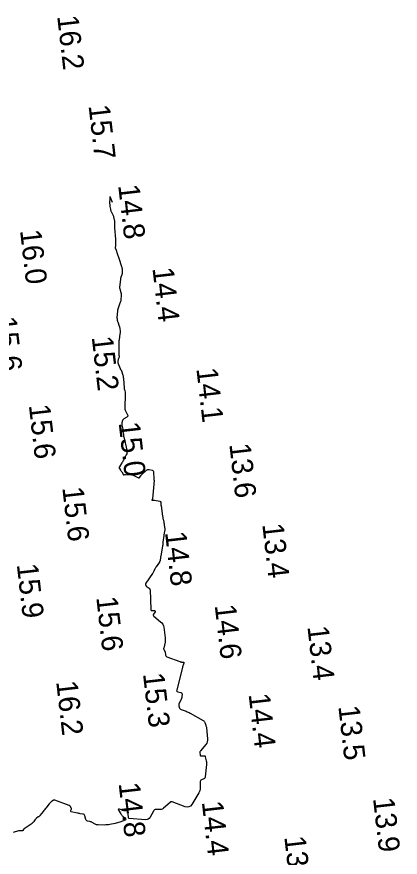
# Model space of a CAD drawing. Extents: x 1023796 to 1112670, y 656573 to 837340.
# Drawn here: x 1109935 to 1110025.3, y 681139.7 to 681337.8 of the extents above; entities that cross this region are included whole.
import ezdxf

# ---------------------------------------------------------------- set-up
doc = ezdxf.new("R2010")
doc.units = 0
doc.layers.add('V-CHAN-CONT-15FT', color=7, linetype='Continuous')
doc.layers.add('V-TOPO-SOUN', color=7, linetype='Continuous')

msp = doc.modelspace()

# ---------------------------------------------------------------- linework, layer by layer
at = {"layer": 'V-CHAN-CONT-15FT'}
msp.add_lwpolyline([(1109957.51, 681294.05), (1109957.04, 681295.22), (1109956.98, 681295.37), (1109956.93, 681295.41), (1109956.9, 681295.35), (1109956.88, 681295.19), (1109956.87, 681293.8), (1109956.88, 681293.64), (1109956.88, 681293.48), (1109956.9, 681293.31), (1109956.93, 681293.15), (1109957.04, 681292.51), (1109957.07, 681292.35), (1109957.12, 681292.19), (1109957.18, 681292.04), (1109957.24, 681291.9), (1109957.55, 681291.29), (1109957.62, 681291.14), (1109957.69, 681290.99), (1109957.74, 681290.83), (1109957.78, 681290.67), (1109957.95, 681289.97), (1109957.99, 681289.81), (1109958.01, 681289.66), (1109958.02, 681289.51), (1109958.02, 681289.36), (1109958.02, 681288.74), (1109958.02, 681288.59), (1109958.03, 681288.43), (1109958.03, 681288.28), (1109958.04, 681288.12), (1109958.24, 681285.41), (1109958.25, 681285.27), (1109958.26, 681285.13), (1109958.26, 681284.98), (1109958.26, 681284.84), (1109958.26, 681284.13), (1109958.25, 681284.05), (1109958.25, 681283.98), (1109958.24, 681283.9), (1109958.23, 681283.82), (1109958.18, 681283.43), (1109958.18, 681283.4), (1109958.18, 681283.37), (1109958.19, 681283.34), (1109958.2, 681283.3), (1109958.25, 681283.18), (1109958.26, 681283.15), (1109958.27, 681283.12), (1109958.28, 681283.09), (1109958.3, 681283.06), (1109958.73, 681281.81), (1109958.8, 681281.6), (1109958.88, 681281.38), (1109958.95, 681281.16), (1109959.03, 681280.94), (1109959.69, 681278.95), (1109959.74, 681278.78), (1109959.77, 681278.62), (1109959.79, 681278.45), (1109959.8, 681278.29), (1109959.82, 681277.56), (1109959.82, 681277.42), (1109959.8, 681277.28), (1109959.77, 681277.14), (1109959.73, 681277), (1109959.54, 681276.46), (1109959.5, 681276.32), (1109959.46, 681276.19), (1109959.43, 681276.05), (1109959.41, 681275.91), (1109959.21, 681274.11), (1109959.2, 681274.02), (1109959.21, 681273.93), (1109959.22, 681273.84), (1109959.24, 681273.75), (1109959.35, 681273.39), (1109959.37, 681273.3), (1109959.4, 681273.21), (1109959.42, 681273.13), (1109959.45, 681273.04), (1109959.55, 681272.61), (1109959.58, 681272.51), (1109959.59, 681272.4), (1109959.59, 681272.3), (1109959.59, 681272.2), (1109959.49, 681271.12), (1109959.47, 681270.9), (1109959.42, 681270.69), (1109959.37, 681270.49), (1109959.3, 681270.29), (1109958.94, 681269.36), (1109958.87, 681269.13), (1109958.8, 681268.9), (1109958.76, 681268.67), (1109958.73, 681268.44), (1109958.6, 681266.98), (1109958.6, 681266.89), (1109958.6, 681266.8), (1109958.61, 681266.71), (1109958.62, 681266.62), (1109958.68, 681266.26), (1109958.7, 681266.17), (1109958.72, 681266.09), (1109958.75, 681266), (1109958.78, 681265.91), (1109959.14, 681264.94), (1109959.19, 681264.79), (1109959.22, 681264.63), (1109959.25, 681264.48), (1109959.27, 681264.32), (1109959.32, 681263.69), (1109959.33, 681263.53), (1109959.33, 681263.37), (1109959.32, 681263.22), (1109959.3, 681263.06), (1109959.1, 681261.71), (1109959.06, 681261.44), (1109959.03, 681261.16), (1109959.02, 681260.88), (1109959.01, 681260.6), (1109959.02, 681258.24), (1109959.03, 681258.19), (1109959.03, 681258.14), (1109959.04, 681258.08), (1109959.05, 681258.03), (1109959.11, 681257.83), (1109959.12, 681257.78), (1109959.13, 681257.73), (1109959.12, 681257.68), (1109959.1, 681257.63), (1109958.96, 681257.3), (1109958.93, 681257.23), (1109958.9, 681257.16), (1109958.88, 681257.09), (1109958.86, 681257.01), (1109958.79, 681256.64), (1109958.78, 681256.55), (1109958.79, 681256.46), (1109958.8, 681256.38), (1109958.82, 681256.3), (1109959.33, 681254.9), (1109959.35, 681254.85), (1109959.38, 681254.8), (1109959.41, 681254.76), (1109959.44, 681254.71), (1109959.57, 681254.54), (1109959.61, 681254.5), (1109959.63, 681254.45), (1109959.66, 681254.4), (1109959.67, 681254.35), (1109959.97, 681253.35), (1109960.02, 681253.16), (1109960.06, 681252.97), (1109960.09, 681252.78), (1109960.11, 681252.59), (1109960.3, 681250.27), (1109960.3, 681250.22), (1109960.31, 681250.17), (1109960.32, 681250.12), (1109960.33, 681250.07), (1109960.39, 681249.89), (1109960.4, 681249.84), (1109960.41, 681249.79), (1109960.42, 681249.74), (1109960.43, 681249.7), (1109960.5, 681249.3), (1109960.51, 681249.22), (1109960.52, 681249.13), (1109960.53, 681249.05), (1109960.53, 681248.97), (1109960.47, 681245.54), (1109960.48, 681245.33), (1109960.52, 681245.14), (1109960.58, 681244.95), (1109960.67, 681244.76), (1109961.09, 681243.99), (1109961.15, 681243.84), (1109961.14, 681243.7), (1109961.08, 681243.59), (1109960.95, 681243.49), (1109960.24, 681243.09), (1109960.13, 681243.01), (1109960.03, 681242.91), (1109959.96, 681242.8), (1109959.92, 681242.67), (1109959.78, 681242.1), (1109959.75, 681241.96), (1109959.74, 681241.82), (1109959.75, 681241.68), (1109959.77, 681241.54), (1109959.99, 681240.59), (1109959.99, 681240.55), (1109959.98, 681240.51), (1109959.96, 681240.47), (1109959.93, 681240.45), (1109959.76, 681240.34), (1109959.73, 681240.31), (1109959.72, 681240.28), (1109959.73, 681240.25), (1109959.75, 681240.22), (1109959.95, 681240.02), (1109959.98, 681239.97), (1109960.01, 681239.92), (1109960.04, 681239.87), (1109960.05, 681239.81), (1109960.11, 681239.26), (1109960.12, 681239.14), (1109960.14, 681239.03), (1109960.16, 681238.92), (1109960.19, 681238.81), (1109960.91, 681235.65), (1109960.95, 681235.37), (1109960.95, 681235.1), (1109960.89, 681234.84), (1109960.79, 681234.59), (1109960.21, 681233.46), (1109960.11, 681233.26), (1109960, 681233.07), (1109959.89, 681232.88), (1109959.77, 681232.69), (1109959.19, 681231.76), (1109959.14, 681231.66), (1109959.12, 681231.56), (1109959.14, 681231.46), (1109959.19, 681231.36), (1109959.45, 681230.96), (1109959.52, 681230.86), (1109959.58, 681230.76), (1109959.65, 681230.66), (1109959.71, 681230.56), (1109960.15, 681229.89), (1109960.18, 681229.86), (1109960.21, 681229.84), (1109960.24, 681229.84), (1109960.28, 681229.85), (1109960.43, 681229.92), (1109960.47, 681229.94), (1109960.51, 681229.95), (1109960.55, 681229.95), (1109960.59, 681229.95), (1109962, 681229.85), (1109962.2, 681229.82), (1109962.39, 681229.78), (1109962.57, 681229.71), (1109962.76, 681229.63), (1109963.63, 681229.16), (1109963.72, 681229.13), (1109963.8, 681229.13), (1109963.88, 681229.17), (1109963.94, 681229.25), (1109964.18, 681229.62), (1109964.24, 681229.71), (1109964.31, 681229.8), (1109964.39, 681229.88), (1109964.47, 681229.96), (1109965.56, 681230.94), (1109965.7, 681231.03), (1109965.85, 681231.09), (1109966.01, 681231.11), (1109966.17, 681231.1), (1109966.87, 681230.95), (1109967.02, 681230.89), (1109967.13, 681230.8), (1109967.19, 681230.68), (1109967.22, 681230.52), (1109967.25, 681228.95), (1109967.25, 681228.91), (1109967.25, 681228.87), (1109967.26, 681228.83), (1109967.27, 681228.79), (1109967.31, 681228.64), (1109967.32, 681228.6), (1109967.32, 681228.56), (1109967.32, 681228.53), (1109967.32, 681228.49), (1109966.97, 681224.22), (1109966.97, 681224.18), (1109966.96, 681224.15), (1109966.94, 681224.11), (1109966.92, 681224.08), (1109966.83, 681223.95), (1109966.82, 681223.93), (1109966.82, 681223.91), (1109966.84, 681223.89), (1109966.87, 681223.89), (1109967.16, 681223.88), (1109967.22, 681223.87), (1109967.29, 681223.87), (1109967.35, 681223.86), (1109967.41, 681223.85), (1109968.69, 681223.64), (1109968.78, 681223.61), (1109968.85, 681223.56), (1109968.9, 681223.49), (1109968.92, 681223.39), (1109968.95, 681222.96), (1109968.95, 681222.85), (1109968.96, 681222.74), (1109968.98, 681222.63), (1109968.99, 681222.53), (1109969.33, 681220.11), (1109969.36, 681219.94), (1109969.39, 681219.76), (1109969.42, 681219.58), (1109969.46, 681219.4), (1109969.61, 681218.69), (1109969.64, 681218.52), (1109969.68, 681218.34), (1109969.7, 681218.16), (1109969.73, 681217.98), (1109969.83, 681217.13), (1109969.84, 681217), (1109969.84, 681216.86), (1109969.83, 681216.73), (1109969.81, 681216.6), (1109969.7, 681216.08), (1109969.68, 681215.94), (1109969.66, 681215.81), (1109969.63, 681215.68), (1109969.61, 681215.55), (1109969.4, 681213.96), (1109969.39, 681213.89), (1109969.38, 681213.81), (1109969.38, 681213.74), (1109969.37, 681213.66), (1109969.36, 681213.36), (1109969.36, 681213.28), (1109969.35, 681213.2), (1109969.34, 681213.13), (1109969.33, 681213.05), (1109968.91, 681210.78), (1109968.89, 681210.65), (1109968.87, 681210.52), (1109968.85, 681210.39), (1109968.83, 681210.26), (1109968.76, 681209.75), (1109968.74, 681209.62), (1109968.7, 681209.5), (1109968.65, 681209.39), (1109968.58, 681209.28), (1109967.82, 681208.2), (1109967.73, 681208.07), (1109967.66, 681207.94), (1109967.59, 681207.8), (1109967.52, 681207.67), (1109967.28, 681207.11), (1109967.22, 681206.97), (1109967.15, 681206.84), (1109967.07, 681206.71), (1109966.99, 681206.58), (1109965.39, 681204.29), (1109965.38, 681204.27), (1109965.36, 681204.25), (1109965.35, 681204.23), (1109965.34, 681204.21), (1109965.29, 681204.13), (1109965.28, 681204.1), (1109965.28, 681204.08), (1109965.28, 681204.06), (1109965.28, 681204.04), (1109965.39, 681203.79), (1109965.41, 681203.74), (1109965.44, 681203.7), (1109965.47, 681203.66), (1109965.51, 681203.63), (1109966.14, 681203.18), (1109966.24, 681203.09), (1109966.32, 681202.98), (1109966.36, 681202.86), (1109966.38, 681202.73), (1109966.54, 681198.13), (1109966.56, 681198.01), (1109966.62, 681197.91), (1109966.72, 681197.86), (1109966.84, 681197.84), (1109967.43, 681197.84), (1109967.55, 681197.82), (1109967.61, 681197.78), (1109967.61, 681197.7), (1109967.56, 681197.59), (1109967.19, 681197.02), (1109967.13, 681196.89), (1109967.12, 681196.76), (1109967.16, 681196.65), (1109967.26, 681196.54), (1109968.88, 681195.22), (1109969.16, 681194.95), (1109969.38, 681194.64), (1109969.53, 681194.3), (1109969.62, 681193.91), (1109969.95, 681191.44), (1109969.97, 681191.18), (1109969.97, 681190.91), (1109969.95, 681190.65), (1109969.91, 681190.39), (1109969.6, 681188.99), (1109969.59, 681188.92), (1109969.59, 681188.84), (1109969.61, 681188.76), (1109969.64, 681188.69), (1109969.81, 681188.4), (1109969.85, 681188.33), (1109969.88, 681188.26), (1109969.9, 681188.18), (1109969.92, 681188.1), (1109970.04, 681187.36), (1109970.08, 681187.22), (1109970.15, 681187.11), (1109970.25, 681187.02), (1109970.37, 681186.95), (1109973.42, 681185.82), (1109973.51, 681185.78), (1109973.61, 681185.76), (1109973.71, 681185.74), (1109973.82, 681185.72), (1109974.23, 681185.68), (1109974.31, 681185.66), (1109974.36, 681185.62), (1109974.37, 681185.56), (1109974.35, 681185.47), (1109974.15, 681184.98), (1109974.11, 681184.87), (1109974.07, 681184.75), (1109974.03, 681184.64), (1109974, 681184.52), (1109972.66, 681179.12), (1109972.65, 681178.97), (1109972.68, 681178.85), (1109972.77, 681178.76), (1109972.91, 681178.7), (1109973.64, 681178.51), (1109973.76, 681178.46), (1109973.84, 681178.39), (1109973.89, 681178.29), (1109973.91, 681178.16), (1109973.9, 681177.6), (1109973.89, 681177.46), (1109973.87, 681177.32), (1109973.83, 681177.19), (1109973.78, 681177.06), (1109973.19, 681175.86), (1109973.14, 681175.74), (1109973.13, 681175.62), (1109973.13, 681175.49), (1109973.17, 681175.37), (1109973.35, 681174.88), (1109973.41, 681174.76), (1109973.48, 681174.67), (1109973.58, 681174.59), (1109973.69, 681174.54), (1109974.9, 681174.11), (1109975.13, 681174.01), (1109975.37, 681173.91), (1109975.6, 681173.8), (1109975.83, 681173.68), (1109978.89, 681171.93), (1109979.02, 681171.84), (1109979.13, 681171.73), (1109979.22, 681171.6), (1109979.29, 681171.46), (1109979.51, 681170.83), (1109979.56, 681170.67), (1109979.6, 681170.51), (1109979.64, 681170.35), (1109979.66, 681170.19), (1109979.91, 681167.65), (1109979.92, 681167.28), (1109979.85, 681166.94), (1109979.72, 681166.62), (1109979.52, 681166.32), (1109978.25, 681164.76), (1109978.18, 681164.66), (1109978.14, 681164.55), (1109978.12, 681164.44), (1109978.12, 681164.32), (1109978.16, 681163.83), (1109978.19, 681163.73), (1109978.24, 681163.65), (1109978.32, 681163.61), (1109978.43, 681163.61), (1109979.03, 681163.65), (1109979.16, 681163.64), (1109979.26, 681163.59), (1109979.33, 681163.51), (1109979.38, 681163.39), (1109979.63, 681162.42), (1109979.67, 681162.22), (1109979.7, 681162.01), (1109979.7, 681161.8), (1109979.69, 681161.59), (1109979.38, 681158.69), (1109979.34, 681158.54), (1109979.28, 681158.41), (1109979.18, 681158.3), (1109979.05, 681158.22), (1109978.48, 681157.92), (1109978.35, 681157.84), (1109978.26, 681157.73), (1109978.21, 681157.6), (1109978.19, 681157.45), (1109978.18, 681156.01), (1109978.16, 681155.72), (1109978.1, 681155.44), (1109978.01, 681155.18), (1109977.87, 681154.92), (1109976.23, 681152.17), (1109975.92, 681151.78), (1109975.55, 681151.56), (1109975.12, 681151.5), (1109974.63, 681151.61), (1109971.57, 681152.76), (1109971.55, 681152.76), (1109971.53, 681152.77), (1109971.51, 681152.77), (1109971.49, 681152.76), (1109971.41, 681152.75), (1109971.4, 681152.75), (1109971.38, 681152.75), (1109971.36, 681152.75), (1109971.34, 681152.75), (1109971.26, 681152.75), (1109971.24, 681152.75), (1109971.23, 681152.75), (1109971.21, 681152.74), (1109971.2, 681152.73), (1109971.16, 681152.66), (1109971.15, 681152.64), (1109971.13, 681152.63), (1109971.12, 681152.62), (1109971.11, 681152.6), (1109969.58, 681151.26), (1109969.39, 681151.12), (1109969.2, 681151.03), (1109968.99, 681150.97), (1109968.76, 681150.96), (1109967.84, 681150.97), (1109967.62, 681150.95), (1109967.44, 681150.88), (1109967.28, 681150.75), (1109967.16, 681150.57), (1109966.38, 681149.13), (1109966.19, 681148.86), (1109965.95, 681148.68), (1109965.67, 681148.58), (1109965.34, 681148.56), (1109961.44, 681148.85), (1109961.41, 681148.85), (1109961.39, 681148.86), (1109961.38, 681148.88), (1109961.37, 681148.9), (1109961.33, 681148.99), (1109961.32, 681149.02), (1109961.31, 681149.04), (1109961.31, 681149.07), (1109961.3, 681149.09), (1109961.15, 681150.73), (1109961.14, 681150.81), (1109961.1, 681150.85), (1109961.05, 681150.86), (1109960.98, 681150.83), (1109960.66, 681150.68), (1109960.58, 681150.65), (1109960.5, 681150.64), (1109960.41, 681150.64), (1109960.33, 681150.66), (1109959.18, 681151.02), (1109959.01, 681151.06), (1109958.92, 681151.03), (1109958.91, 681150.93), (1109958.99, 681150.77), (1109959.5, 681149.94), (1109959.61, 681149.78), (1109959.73, 681149.64), (1109959.85, 681149.5), (1109959.99, 681149.37), (1109960.56, 681148.87), (1109960.66, 681148.75), (1109960.68, 681148.65), (1109960.63, 681148.56), (1109960.49, 681148.48), (1109959.25, 681148), (1109958.98, 681147.91), (1109958.71, 681147.82), (1109958.44, 681147.75), (1109958.16, 681147.69), (1109956.91, 681147.43), (1109956.6, 681147.37), (1109956.3, 681147.34), (1109955.99, 681147.32), (1109955.69, 681147.31), (1109954.16, 681147.33), (1109953.98, 681147.34), (1109953.8, 681147.38), (1109953.64, 681147.43), (1109953.47, 681147.51), (1109952.78, 681147.92), (1109952.65, 681147.99), (1109952.51, 681148.04), (1109952.37, 681148.09), (1109952.23, 681148.12), (1109951.65, 681148.24), (1109951.51, 681148.28), (1109951.41, 681148.35), (1109951.32, 681148.45), (1109951.27, 681148.58), (1109950.99, 681149.51), (1109950.92, 681149.65), (1109950.84, 681149.76), (1109950.72, 681149.83), (1109950.57, 681149.88), (1109949.94, 681149.98), (1109949.78, 681150.01), (1109949.62, 681150.04), (1109949.46, 681150.07), (1109949.31, 681150.11), (1109947.82, 681150.44), (1109947.75, 681150.47), (1109947.71, 681150.51), (1109947.7, 681150.57), (1109947.72, 681150.65), (1109947.85, 681150.98), (1109947.88, 681151.06), (1109947.88, 681151.14), (1109947.87, 681151.22), (1109947.84, 681151.3), (1109947.64, 681151.68), (1109947.59, 681151.76), (1109947.53, 681151.83), (1109947.45, 681151.89), (1109947.36, 681151.93), (1109943.97, 681153.18), (1109943.88, 681153.2), (1109943.8, 681153.2), (1109943.72, 681153.18), (1109943.65, 681153.15), (1109943.33, 681152.94), (1109943.26, 681152.9), (1109943.2, 681152.85), (1109943.14, 681152.8), (1109943.09, 681152.75), (1109942.86, 681152.53), (1109942.81, 681152.48), (1109942.75, 681152.42), (1109942.7, 681152.36), (1109942.65, 681152.3), (1109941.83, 681151.28), (1109941.67, 681151.09), (1109941.52, 681150.9), (1109941.37, 681150.71), (1109941.22, 681150.52), (1109940.43, 681149.52), (1109940.35, 681149.43), (1109940.27, 681149.35), (1109940.17, 681149.27), (1109940.07, 681149.2), (1109939.67, 681148.94), (1109939.57, 681148.87), (1109939.48, 681148.8), (1109939.4, 681148.71), (1109939.33, 681148.61), (1109938.99, 681148.1), (1109938.91, 681147.99), (1109938.81, 681147.88), (1109938.71, 681147.79), (1109938.6, 681147.7), (1109936.71, 681146.4), (1109936.66, 681146.36), (1109936.62, 681146.32), (1109936.59, 681146.28), (1109936.56, 681146.23), (1109936.44, 681146.04), (1109936.41, 681146), (1109936.37, 681145.97), (1109936.32, 681145.95), (1109936.27, 681145.94), (1109935.81, 681145.95), (1109935.71, 681145.95), (1109935.62, 681145.94), (1109935.53, 681145.92), (1109935.43, 681145.9), (1109934.14, 681145.55)], dxfattribs=at)

# ---------------------------------------------------------------- texts
at = {"layer": 'V-TOPO-SOUN'}
for s, p in [('16.2 ', (1109944.5, 681337.99)), ('15.7 ', (1109951.89, 681316.9)), ('14.8 ', (1109958.87, 681298.1)), ('16.0 ', (1109935.76, 681287.47)), ('14.4 ', (1109966.94, 681278.58)), ('15.6 ', (1109929.93, 681266.95)), ('15.2 ', (1109952.64, 681262.34)), ('14.1 ', (1109977.28, 681254.89)), ('15.6 ', (1109937.83, 681246.28)), ('15.0 ', (1109958.98, 681242.13)), ('13.6 ', (1109985.04, 681237.09)), ('15.6 ', (1109945.71, 681226.83)), ('13.4 ', (1109992.8, 681218.21)), ('14.8 ', (1109969.9, 681216.31)), ('15.9 ', (1109934.99, 681208.73)), ('15.6 ', (1109953.71, 681200.97)), ('14.6 ', (1109981.6, 681199.1)), ('13.4 ', (1110003.43, 681194.06)), ('15.3 ', (1109964.71, 681182.97)), ('16.2 ', (1109944.27, 681181.1)), ('14.4 ', (1109989.58, 681178.15)), ('13.5 ', (1110010.71, 681175.27)), ('14.8 ', (1109958.97, 681157.12)), ('14.4 ', (1109978.56, 681152.76)), ('13.9 ', (1110018.88, 681153.58)), ('13.8 ', (1109997.98, 681144.52))]:
    msp.add_text(s, height=5, rotation=276.5594, dxfattribs=at).set_placement(p)

doc.saveas('drawing.dxf')
